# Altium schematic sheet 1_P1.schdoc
size 426 x 302 mm; Symbol: Sheet_A3_Whycan; Device: Sheet_A3; @Project Name: Avaota Pi A; REV: 1.0; Company: YuzukiHD; Draw By: GloomyGhost; @Update Date: 2024-02-14; @Page No: 1; @Page Count: 1
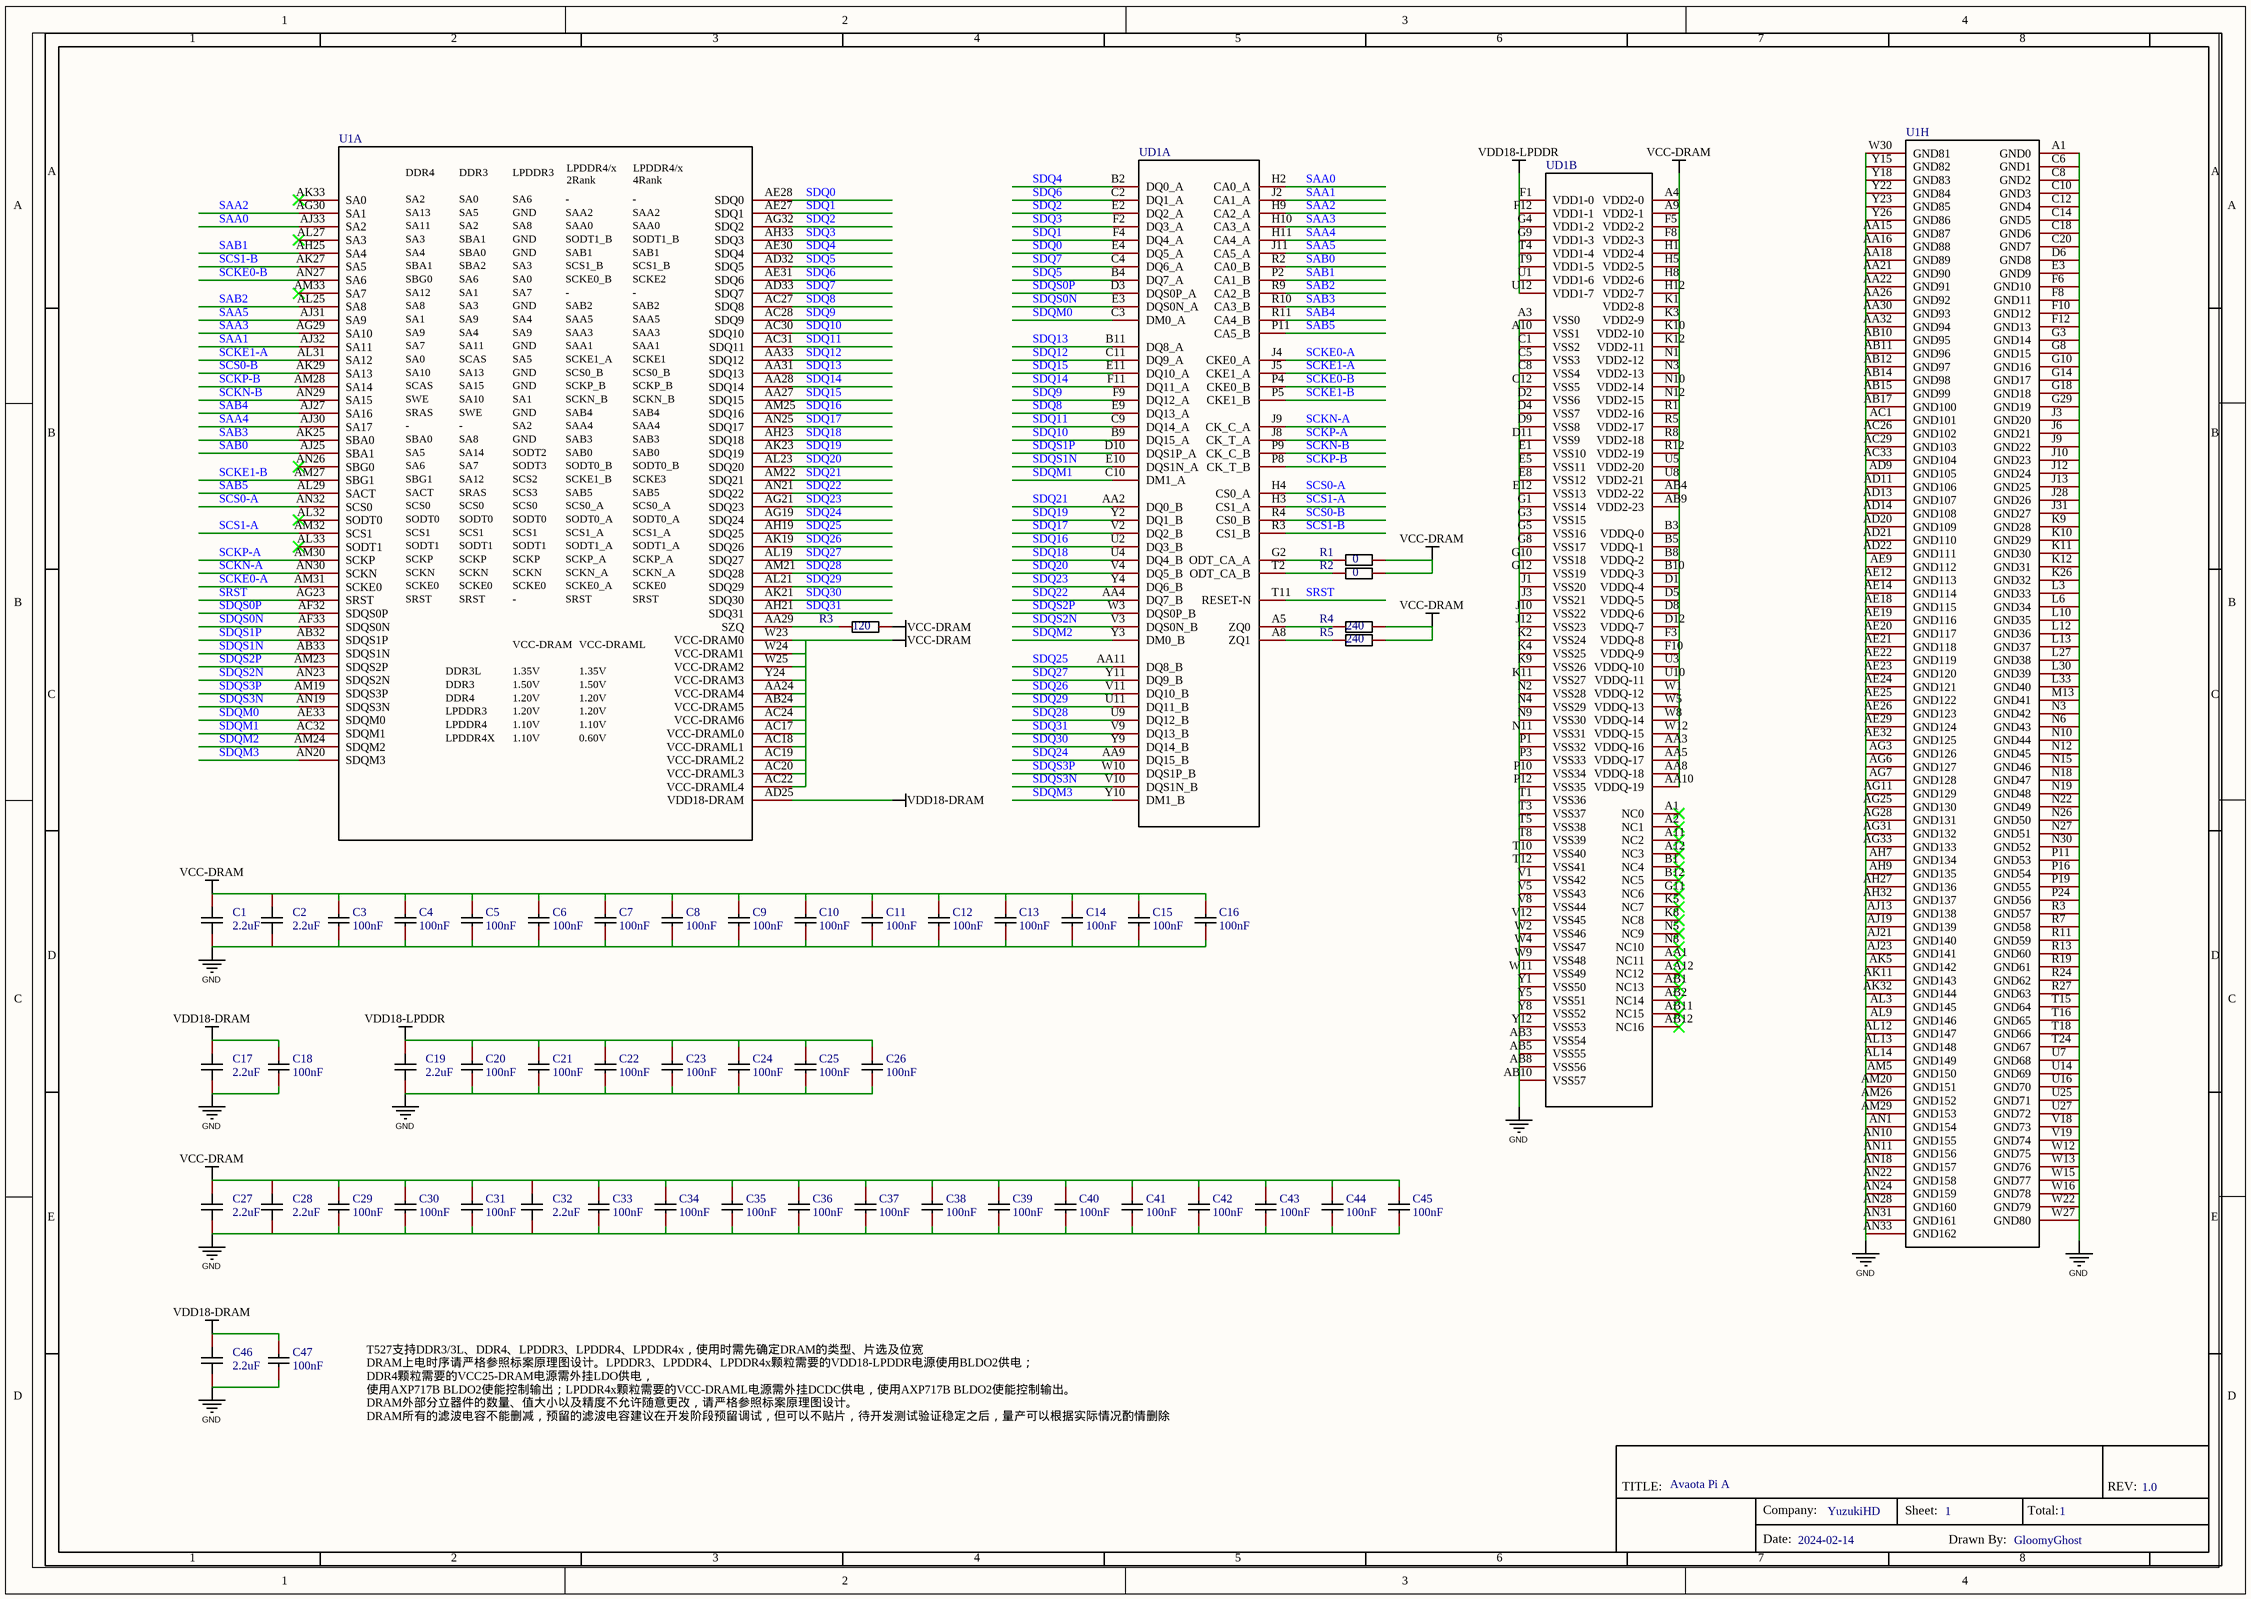
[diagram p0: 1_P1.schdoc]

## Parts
C1  2.2uF  [c0201 nsk]
C2  2.2uF  [c0201 nsk]
C3  100nF  [c0201 nsk]
C4  100nF  [c0201 nsk]
C5  100nF  [c0201 nsk]
C6  100nF  [c0201 nsk]
C7  100nF  [c0201 nsk]
C8  100nF  [c0201 nsk]
C9  100nF  [c0201 nsk]
C10  100nF  [c0201 nsk]
C11  100nF  [c0201 nsk]
C12  100nF  [c0201 nsk]
C13  100nF  [c0201 nsk]
C14  100nF  [c0201 nsk]
C15  100nF  [c0201 nsk]
C16  100nF  [c0201 nsk]
C17  2.2uF  [c0201 nsk]
C18  100nF  [c0201 nsk]
C19  2.2uF  [c0201 nsk]
C20  100nF  [c0201 nsk]
C21  100nF  [c0201 nsk]
C22  100nF  [c0201 nsk]
C23  100nF  [c0201 nsk]
C24  100nF  [c0201 nsk]
C25  100nF  [c0201 nsk]
C26  100nF  [c0201 nsk]
C27  2.2uF  [c0201 nsk]
C28  2.2uF  [c0201 nsk]
C29  100nF  [c0201 nsk]
C30  100nF  [c0201 nsk]
C31  100nF  [c0201 nsk]
C32  2.2uF  [c0201 nsk]
C33  100nF  [c0201 nsk]
C34  100nF  [c0201 nsk]
C35  100nF  [c0201 nsk]
C36  100nF  [c0201 nsk]
C37  100nF  [c0201 nsk]
C38  100nF  [c0201 nsk]
C39  100nF  [c0201 nsk]
C40  100nF  [c0201 nsk]
C41  100nF  [c0201 nsk]
C42  100nF  [c0201 nsk]
C43  100nF  [c0201 nsk]
C44  100nF  [c0201 nsk]
C45  100nF  [c0201 nsk]
C46  2.2uF  [c0201 nsk]
C47  100nF  [c0201 nsk]
R1  0  [r0201 nsk]
R2  0  [r0201 nsk]
R3  120  [r0201 nsk]
R4  240  [r0201 nsk]
R5  240  [r0201 nsk]
U1  T527  [T527-BGA664]  (value not drawn)  (parts A,H of 8)
UD1  LPDDR4_FBGA200  [BGA200P65_80B1000_1500H90]  (value not drawn)  (parts A,B of 2)

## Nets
GND: C1.2 C2.2 C3.1 C4.1 C5.1 C6.1 C7.1 C8.1 C9.1 C10.1 C11.1 C12.1 C13.1 C14.1 C15.1 C16.1 C17.2 C18.1 C19.2 C20.1 C21.1 C22.1 C23.1 C24.1 C25.1 C26.1 C27.2 C28.2 C29.1 C30.1 C31.1 C32.2 C33.1 C34.1 C35.1 C36.1 C37.1 C38.1 C39.1 C40.1 C41.1 C42.1 C43.1 C44.1 C45.1 C46.2 C47.1 U1.A1(GND0) U1.AA15(GND87) U1.AA16(GND88) U1.AA18(GND89) U1.AA21(GND90) U1.AA22(GND91) U1.AA26(GND92) U1.AA30(GND93) U1.AA32(GND94) U1.AB10(GND95) U1.AB11(GND96) U1.AB12(GND97) U1.AB14(GND98) U1.AB15(GND99) U1.AB17(GND100) U1.AC1(GND101) U1.AC26(GND102) U1.AC29(GND103) U1.AC33(GND104) U1.AD9(GND105) U1.AD11(GND106) U1.AD13(GND107) U1.AD14(GND108) U1.AD20(GND109) U1.AD21(GND110) U1.AD22(GND111) U1.AE9(GND112) U1.AE12(GND113) U1.AE14(GND114) U1.AE18(GND115) U1.AE19(GND116) U1.AE20(GND117) U1.AE21(GND118) U1.AE22(GND119) U1.AE23(GND120) U1.AE24(GND121) U1.AE25(GND122) U1.AE26(GND123) U1.AE29(GND124) U1.AE32(GND125) U1.AG3(GND126) U1.AG6(GND127) U1.AG7(GND128) U1.AG11(GND129) U1.AG25(GND130) U1.AG28(GND131) U1.AG31(GND132) U1.AG33(GND133) U1.AH7(GND134) U1.AH9(GND135) U1.AH27(GND136) U1.AH32(GND137) U1.AJ13(GND138) U1.AJ19(GND139) U1.AJ21(GND140) U1.AJ23(GND141) U1.AK5(GND142) U1.AK11(GND143) U1.AK32(GND144) U1.AL3(GND145) U1.AL9(GND146) U1.AL12(GND147) U1.AL13(GND148) U1.AL14(GND149) U1.AM5(GND150) U1.AM20(GND151) U1.AM26(GND152) U1.AM29(GND153) U1.AN1(GND154) U1.AN10(GND155) U1.AN11(GND156) U1.AN18(GND157) U1.AN22(GND158) U1.AN24(GND159) U1.AN28(GND160) U1.AN31(GND161) U1.AN33(GND162) U1.C6(GND1) U1.C8(GND2) U1.C10(GND3) U1.C12(GND4) U1.C14(GND5) U1.C18(GND6) U1.C20(GND7) U1.D6(GND8) U1.E3(GND9) U1.F6(GND10) U1.F8(GND11) U1.F10(GND12) U1.F12(GND13) U1.G3(GND14) U1.G8(GND15) U1.G10(GND16) U1.G14(GND17) U1.G18(GND18) U1.G29(GND19) U1.J3(GND20) U1.J6(GND21) U1.J9(GND22) U1.J10(GND23) U1.J12(GND24) U1.J13(GND25) U1.J28(GND26) U1.J31(GND27) U1.K9(GND28) U1.K10(GND29) U1.K11(GND30) U1.K12(GND31) U1.K26(GND32) U1.L3(GND33) U1.L6(GND34) U1.L10(GND35) U1.L12(GND36) U1.L13(GND37) U1.L27(GND38) U1.L30(GND39) U1.L33(GND40) U1.M13(GND41) U1.N3(GND42) U1.N6(GND43) U1.N10(GND44) U1.N12(GND45) U1.N15(GND46) U1.N18(GND47) U1.N19(GND48) U1.N22(GND49) U1.N26(GND50) U1.N27(GND51) U1.N30(GND52) U1.P11(GND53) U1.P16(GND54) U1.P19(GND55) U1.P24(GND56) U1.R3(GND57) U1.R7(GND58) U1.R11(GND59) U1.R13(GND60) U1.R19(GND61) U1.R24(GND62) U1.R27(GND63) U1.T15(GND64) U1.T16(GND65) U1.T18(GND66) U1.T24(GND67) U1.U7(GND68) U1.U14(GND69) U1.U16(GND70) U1.U25(GND71) U1.U27(GND72) U1.V18(GND73) U1.V19(GND74) U1.W12(GND75) U1.W13(GND76) U1.W15(GND77) U1.W16(GND78) U1.W22(GND79) U1.W27(GND80) U1.W30(GND81) U1.Y15(GND82) U1.Y18(GND83) U1.Y22(GND84) U1.Y23(GND85) U1.Y26(GND86) UD1.A3(VSS0) UD1.A10(VSS1) UD1.AB3(VSS54) UD1.AB5(VSS55) UD1.AB8(VSS56) UD1.AB10(VSS57) UD1.C1(VSS2) UD1.C5(VSS3) UD1.C8(VSS4) UD1.C12(VSS5) UD1.D2(VSS6) UD1.D4(VSS7) UD1.D9(VSS8) UD1.D11(VSS9) UD1.E1(VSS10) UD1.E5(VSS11) UD1.E8(VSS12) UD1.E12(VSS13) UD1.G1(VSS14) UD1.G3(VSS15) UD1.G5(VSS16) UD1.G8(VSS17) UD1.G10(VSS18) UD1.G12(VSS19) UD1.J1(VSS20) UD1.J3(VSS21) UD1.J10(VSS22) UD1.J12(VSS23) UD1.K2(VSS24) UD1.K4(VSS25) UD1.K9(VSS26) UD1.K11(VSS27) UD1.N2(VSS28) UD1.N4(VSS29) UD1.N9(VSS30) UD1.N11(VSS31) UD1.P1(VSS32) UD1.P3(VSS33) UD1.P10(VSS34) UD1.P12(VSS35) UD1.T1(VSS36) UD1.T3(VSS37) UD1.T5(VSS38) UD1.T8(VSS39) UD1.T10(VSS40) UD1.T12(VSS41) UD1.V1(VSS42) UD1.V5(VSS43) UD1.V8(VSS44) UD1.V12(VSS45) UD1.W2(VSS46) UD1.W4(VSS47) UD1.W9(VSS48) UD1.W11(VSS49) UD1.Y1(VSS50) UD1.Y5(VSS51) UD1.Y8(VSS52) UD1.Y12(VSS53)
VCC-DRAM: C1.1 C2.1 C3.2 C4.2 C5.2 C6.2 C7.2 C8.2 C9.2 C10.2 C11.2 C12.2 C13.2 C14.2 C15.2 C16.2 C27.1 C28.1 C29.2 C30.2 C31.2 C32.1 C33.2 C34.2 C35.2 C36.2 C37.2 C38.2 C39.2 C40.2 C41.2 C42.2 C43.2 C44.2 C45.2 R1.2 R2.2 R3.2 R4.2 R5.2 U1.AA24(VCC-DRAM4) U1.AB24(VCC-DRAM5) U1.AC17(VCC-DRAML0) U1.AC18(VCC-DRAML1) U1.AC19(VCC-DRAML2) U1.AC20(VCC-DRAML3) U1.AC22(VCC-DRAML4) U1.AC24(VCC-DRAM6) U1.W23(VCC-DRAM0) U1.W24(VCC-DRAM1) U1.W25(VCC-DRAM2) U1.Y24(VCC-DRAM3) UD1.A4(VDD2-0) UD1.A9(VDD2-1) UD1.AA3(VDDQ-16) UD1.AA5(VDDQ-17) UD1.AA8(VDDQ-18) UD1.AA10(VDDQ-19) UD1.AB4(VDD2-22) UD1.AB9(VDD2-23) UD1.B3(VDDQ-0) UD1.B5(VDDQ-1) UD1.B8(VDDQ-2) UD1.B10(VDDQ-3) UD1.D1(VDDQ-4) UD1.D5(VDDQ-5) UD1.D8(VDDQ-6) UD1.D12(VDDQ-7) UD1.F3(VDDQ-8) UD1.F5(VDD2-2) UD1.F8(VDD2-3) UD1.F10(VDDQ-9) UD1.H1(VDD2-4) UD1.H5(VDD2-5) UD1.H8(VDD2-6) UD1.H12(VDD2-7) UD1.K1(VDD2-8) UD1.K3(VDD2-9) UD1.K10(VDD2-10) UD1.K12(VDD2-11) UD1.N1(VDD2-12) UD1.N3(VDD2-13) UD1.N10(VDD2-14) UD1.N12(VDD2-15) UD1.R1(VDD2-16) UD1.R5(VDD2-17) UD1.R8(VDD2-18) UD1.R12(VDD2-19) UD1.U3(VDDQ-10) UD1.U5(VDD2-20) UD1.U8(VDD2-21) UD1.U10(VDDQ-11) UD1.W1(VDDQ-12) UD1.W5(VDDQ-13) UD1.W8(VDDQ-14) UD1.W12(VDDQ-15)
VDD18-DRAM: C17.1 C18.2 C46.1 C47.2 U1.AD25(VDD18-DRAM)
VDD18-LPDDR: C19.1 C20.2 C21.2 C22.2 C23.2 C24.2 C25.2 C26.2 UD1.F1(VDD1-0) UD1.F12(VDD1-1) UD1.G4(VDD1-2) UD1.G9(VDD1-3) UD1.T4(VDD1-4) UD1.T9(VDD1-5) UD1.U1(VDD1-6) UD1.U12(VDD1-7)
SAA0: U1.AJ33(SA2) UD1.H2(CA0_A)
SAA1: U1.AJ32(SA11) UD1.J2(CA1_A)
SAA2: U1.AG30(SA1) UD1.H9(CA2_A)
SAA3: U1.AG29(SA10) UD1.H10(CA3_A)
SAA4: U1.AJ30(SA17) UD1.H11(CA4_A)
SAA5: U1.AJ31(SA9) UD1.J11(CA5_A)
SAB0: U1.AJ25(SBA1) UD1.R2(CA0_B)
SAB1: U1.AH25(SA4) UD1.P2(CA1_B)
SAB2: U1.AL25(SA8) UD1.R9(CA2_B)
SAB3: U1.AK25(SBA0) UD1.R10(CA3_B)
SAB4: U1.AJ27(SA16) UD1.R11(CA4_B)
SAB5: U1.AL29(SACT) UD1.P11(CA5_B)
SCKE0-A: U1.AM31(SCKE0) UD1.J4(CKE0_A)
SCKE0-B: U1.AN27(SA6) UD1.P4(CKE0_B)
SCKE1-A: U1.AL31(SA12) UD1.J5(CKE1_A)
SCKE1-B: U1.AM27(SBG1) UD1.P5(CKE1_B)
SCKN-A: U1.AN30(SCKN) UD1.J9(CK_C_A)
SCKN-B: U1.AN29(SA15) UD1.P9(CK_C_B)
SCKP-A: U1.AM30(SCKP) UD1.J8(CK_T_A)
SCKP-B: U1.AM28(SA14) UD1.P8(CK_T_B)
SCS0-A: U1.AN32(SCS0) UD1.H4(CS0_A)
SCS0-B: U1.AK29(SA13) UD1.R4(CS0_B)
SCS1-A: U1.AM32(SCS1) UD1.H3(CS1_A)
SCS1-B: U1.AK27(SA5) UD1.R3(CS1_B)
SDQ0: U1.AE28(SDQ0) UD1.E4(DQ5_A)
SDQ1: U1.AE27(SDQ1) UD1.F4(DQ4_A)
SDQ2: U1.AG32(SDQ2) UD1.E2(DQ2_A)
SDQ3: U1.AH33(SDQ3) UD1.F2(DQ3_A)
SDQ4: U1.AE30(SDQ4) UD1.B2(DQ0_A)
SDQ5: U1.AD32(SDQ5) UD1.B4(DQ7_A)
SDQ6: U1.AE31(SDQ6) UD1.C2(DQ1_A)
SDQ7: U1.AD33(SDQ7) UD1.C4(DQ6_A)
SDQ8: U1.AC27(SDQ8) UD1.E9(DQ13_A)
SDQ9: U1.AC28(SDQ9) UD1.F9(DQ12_A)
SDQ10: U1.AC30(SDQ10) UD1.B9(DQ15_A)
SDQ11: U1.AC31(SDQ11) UD1.C9(DQ14_A)
SDQ12: U1.AA33(SDQ12) UD1.C11(DQ9_A)
SDQ13: U1.AA31(SDQ13) UD1.B11(DQ8_A)
SDQ14: U1.AA28(SDQ14) UD1.F11(DQ11_A)
SDQ15: U1.AA27(SDQ15) UD1.E11(DQ10_A)
SDQ16: U1.AM25(SDQ16) UD1.U2(DQ3_B)
SDQ17: U1.AN25(SDQ17) UD1.V2(DQ2_B)
SDQ18: U1.AH23(SDQ18) UD1.U4(DQ4_B)
SDQ19: U1.AK23(SDQ19) UD1.Y2(DQ1_B)
SDQ20: U1.AL23(SDQ20) UD1.V4(DQ5_B)
SDQ21: U1.AM22(SDQ21) UD1.AA2(DQ0_B)
SDQ22: U1.AN21(SDQ22) UD1.AA4(DQ7_B)
SDQ23: U1.AG21(SDQ23) UD1.Y4(DQ6_B)
SDQ24: U1.AG19(SDQ24) UD1.AA9(DQ15_B)
SDQ25: U1.AH19(SDQ25) UD1.AA11(DQ8_B)
SDQ26: U1.AK19(SDQ26) UD1.V11(DQ10_B)
SDQ27: U1.AL19(SDQ27) UD1.Y11(DQ9_B)
SDQ28: U1.AM21(SDQ28) UD1.U9(DQ12_B)
SDQ29: U1.AL21(SDQ29) UD1.U11(DQ11_B)
SDQ30: U1.AK21(SDQ30) UD1.Y9(DQ14_B)
SDQ31: U1.AH21(SDQ31) UD1.V9(DQ13_B)
SDQM0: U1.AE33(SDQM0) UD1.C3(DM0_A)
SDQM1: U1.AC32(SDQM1) UD1.C10(DM1_A)
SDQM2: U1.AM24(SDQM2) UD1.Y3(DM0_B)
SDQM3: U1.AN20(SDQM3) UD1.Y10(DM1_B)
SDQS0N: U1.AF33(SDQS0N) UD1.E3(DQS0N_A)
SDQS0P: U1.AF32(SDQS0P) UD1.D3(DQS0P_A)
SDQS1N: U1.AB33(SDQS1N) UD1.E10(DQS1N_A)
SDQS1P: U1.AB32(SDQS1P) UD1.D10(DQS1P_A)
SDQS2N: U1.AN23(SDQS2N) UD1.V3(DQS0N_B)
SDQS2P: U1.AM23(SDQS2P) UD1.W3(DQS0P_B)
SDQS3N: U1.AN19(SDQS3N) UD1.V10(DQS1N_B)
SDQS3P: U1.AM19(SDQS3P) UD1.W10(DQS1P_B)
SRST: U1.AG23(SRST) UD1.T11(RESET-N)
NetR1_1: R1.1 UD1.G2(ODT_CA_A)
NetR2_1: R2.1 UD1.T2(ODT_CA_B)
NetR3_1: R3.1 U1.AA29(SZQ)
NetR4_1: R4.1 UD1.A5(ZQ0)
NetR5_1: R5.1 UD1.A8(ZQ1)

Not connected (* = marked no-connect by the designer): U1 AK33(SA0)* AL27(SA3)* AL32(SODT0)* AL33(SODT1)* AM33(SA7)* AN26(SBG0)*; UD1 A1(NC0)* A2(NC1)* A11(NC2)* A12(NC3)* AA1(NC11)* AA12(NC12)* AB1(NC13)* AB2(NC14)* AB11(NC15)* AB12(NC16)* B1(NC4)* B12(NC5)* G11(NC6)* K5(NC7)* K8(NC8)* N5(NC9)* N8(NC10)*

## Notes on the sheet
- T527支持DDR3/3L、DDR4、LPDDR3、LPDDR4、LPDDR4x，使用时需先确定DRAM的类型、片选及位宽
  DRAM上电时序请严格参照标案原理图设计。LPDDR3、LPDDR4、LPDDR4x颗粒需要的VDD18-LPDDR电源使用BLDO2供电；
  DDR4颗粒需要的VCC25-DRAM电源需外挂LDO供电，
  使用AXP717B BLDO2使能控制输出；LPDDR4x颗粒需要的VCC-DRAML电源需外挂DCDC供电，使用AXP717B BLDO2使能控制输出。
  DRAM外部分立器件的数量、值大小以及精度不允许随意更改，请严格参照标案原理图设计。
  DRAM所有的滤波电容不能删减，预留的滤波电容建议在开发阶段预留调试，但可以不贴片，待开发测试验证稳定之后，量产可以根据实际情况酌情删除

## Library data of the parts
C1 C2 C17 C19 C27 C28 C32 C46 = 0201X225M6R3NT: Manufacturer: FH(风华); Add into BOM: yes; Tolerance: ±20%; Voltage Rated: 6.3V; Temperature Coefficient: X5R; Description: 容值:2.2uF;精度:±20%;额定电压:6.3V;材质(温度系数):X5R;
C3-C16 C18 C20-C26 C29-C31 C33-C45 C47 = GRM033R61A104KE15D: Manufacturer: muRata(村田); Add into BOM: yes; Tolerance: ±10%; Voltage Rated: 10V; Temperature Coefficient: X5R; Description: 容值:100nF;精度:±10%;额定电压:10V;材质(温度系数):X5R;
R1-R5 = Res_0201: Symbol: 电阻; Convert to PCB: yes
U1 = T527: Add into BOM: yes; SWAP_INFO: (S1+S2+S3+S4+S5+S6+S7+S8+S9); SPLIT_INST: TRUE; Description: Allwinner T527 SoC
UD1 = LPDDR4_FBGA200: Add into BOM: yes; SWAP_INFO: (S1+S2); SPLIT_INST: TRUE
